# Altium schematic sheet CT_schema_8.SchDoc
size 147 x 119 mm
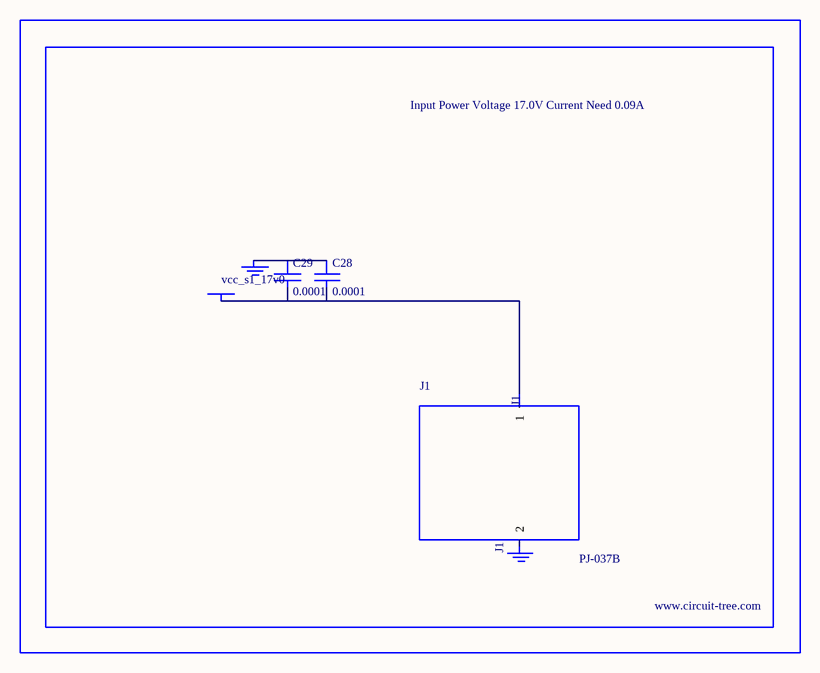
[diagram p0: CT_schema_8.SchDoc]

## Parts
BORDER7  (no value)
C28  0.0001  [EXV-9H]
C29  0.0001  [EXV-9H]
GND_INSTANCE_7_0  (no value)
GND_INSTANCE_7_1  (no value)
J1  PJ-037B  [PJ-037B_PACKAGE]
POWER_INSTANCE_7_0  vcc_s1_17v0

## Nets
NetC28_1: C28.1 C29.1 GND_INSTANCE_7_0.0(GND)
NetC28_2: C28.2 C29.2 J1.1 POWER_INSTANCE_7_0.0(PWR)

Not connected (* = marked no-connect by the designer): GND_INSTANCE_7_1 0(GND); J1 2

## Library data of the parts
BORDER7 = BORDER_PAGE7
C28 C29 = EDK107M035A9HAA
GND_INSTANCE_7_0 GND_INSTANCE_7_1 = GND
POWER_INSTANCE_7_0 = PWR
